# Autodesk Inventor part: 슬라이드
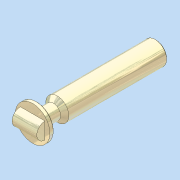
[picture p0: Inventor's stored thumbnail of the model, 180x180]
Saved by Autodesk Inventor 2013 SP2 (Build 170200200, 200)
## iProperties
Company: 한국ATC센터
Created: 2014-10
Part Number: 슬라이드
Document SubType Name: Modeling
Designer: 한국ATC센터
Density: 7.86 g/cm^3
Material: 강, 연강
Mass: 728.405 g
Surface Area: 164.68 cm^2
Volume: 92.6724 cm^3
Author: KYOUNG IL JANG
Revision Number: 1
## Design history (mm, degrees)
sketch "스케치1"
  geometry: L1 (-14, 195)-(-14, 171) reference; L2 (19, 106.5)-(-19, 106.5) reference; L3 (0, 106.5)-(0, 256.5); L4 (0, 256.5)-(-14, 256.5); L5 (-14, 256.5)-(-14, 136.5); L6 (-14, 111.5)-(-21, 111.5); L7 (-21, 111.5)-(-21, 106.5); L8 (-21, 106.5)-(0, 106.5); L9 (-14, 111.5)-(-9, 111.5); L10 (-9, 111.5)-(-9, 131.5); L11 (-9, 131.5)-(-14, 136.5); L12 (-14, 136.5)-(-14, 111.5); 1 further point
  constraints: 24 end point, 5 perpendicular, 3 parallel, 1 collinear, 1 horizontal, 1 midpoint, 1 point on line, 1 vertical, 4 other
  dimensions: "d0" = 5 distance between parallel lines of L6 L8; "d1" = 42 diameter of L7 L3; "d2" = 150 distance of L3.start L3.end; "d3" = 135 deg angle of L11 L5; "d4" = 18 diameter of L10 L3; "d5" = 30 distance from line of L5.end L8
revolve "회전1" sketch "스케치1" stored, may be unused: angle "d6" = 90 deg
chamfer "모따기1" distance "d7" = 1; stored, may be unused: second distance "d8" = 2, angle "d9" = 45 deg
fillet "모깎기1" dims "d10" = 2
sketch "스케치2"
  geometry: L1 (21, 106.5)-(-21, 106.5) reference; L2 (-15, 96.5)-(15, 96.5); L3 (15, 96.5)-(15, 106.5); L4 (15, 106.5)-(-15, 106.5); L5 (-15, 106.5)-(-15, 96.5); 2 further points
  constraints: 8 end point, 2 midpoint, 2 parallel, 1 horizontal, 1 perpendicular, 1 point on line
  dimensions: "d11" = 20 diameter of L2 L4; "d12" = 30 distance between parallel lines of L3 L5
revolve "회전2" sketch "스케치2" stored, may be unused: angle "d13" = 180 deg
node "솔리드1"
